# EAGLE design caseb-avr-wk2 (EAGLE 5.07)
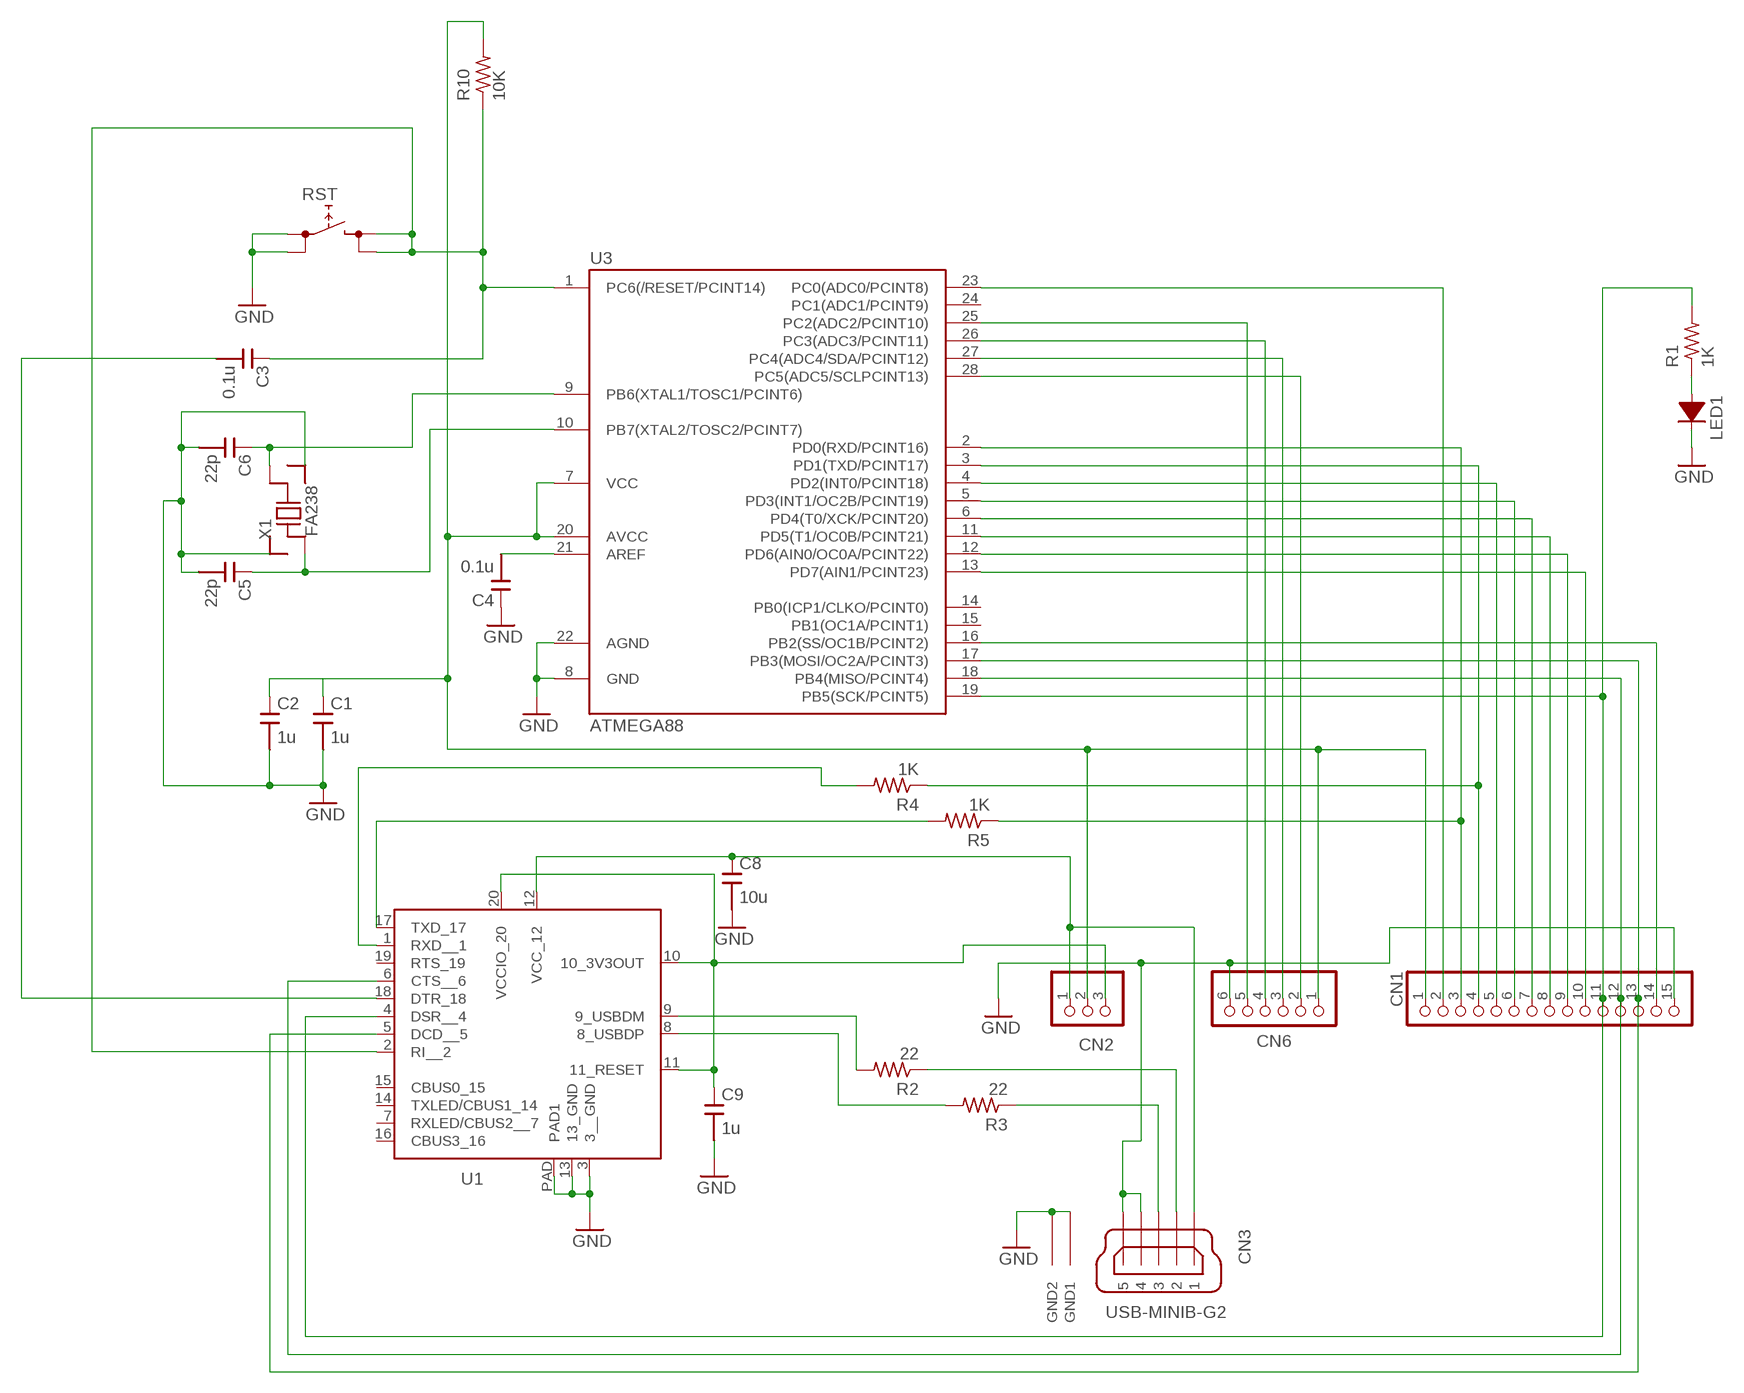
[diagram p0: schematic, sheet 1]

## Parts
C1  1u  C/SMDC2012  [C2012]
C2  1u  C/SMDC2012  [C2012]
C3  0.1u  C/SMDC2012  [C2012]
C4  0.1u  C/SMDC2012  [C2012]
C5  22p  C/SMDC2012  [C2012]
C6  22p  C/SMDC2012  [C2012]
C8  10u  C/SMDC2012  [C2012]
C9  1u  C/SMDC2012  [C2012]
CN1  PINHDR15  [PINHDRX15]
CN2  PINHDR3  [PINHDR1X3]
CN3  USB-MINIB-G2  [USB-MINIBV]
CN6  PINHDR6  [PINHDR1X6]
LED1  D/SMDRB161M  [SOD123]
R1  1K  R/SMDR2012R  [R2012R]
R2  22  R/SMDR2012R  [R2012R]
R3  22  R/SMDR2012R  [R2012R]
R4  1K  R/SMDR2012R  [R2012R]
R5  1K  R/SMDR2012R  [R2012R]
R10  10K  R/SMDR2012R  [R2012R]
RST  TACTSWTACTSW/SMD  [TACTSW/SMD]
U1  FT231XQ  [QFN20]
U3  ATMEGA88  [DIP28]
X1  FA238  [FA238]

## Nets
10_3V3OUT: C9.1 CN2.3 U1.10(10_3V3OUT) U1.11(11_RESET) U1.20(VCCIO_20)
GND [power]: C1.2 C2.2 C4.1 C5.2 C6.2 C8.2 C9.2 CN1.15 CN3.4 CN3.5 CN3.M1(GND1) CN3.M2(GND2) CN6.6 LED1.2(C) RST.1 RST.2 U1.3(3__GND) U1.13(13_GND) U1.PAD(PAD1) U3.8(GND) U3.22(AGND) X1.2 X1.4
N$1: CN1.2 U3.23(PC0(ADC0/PCINT8))
N$2: CN1.14 U3.16(PB2(SS/OC1B/PCINT2))
N$4: CN6.2 U3.28(PC5(ADC5/SCLPCINT13))
N$5: CN6.3 U3.27(PC4(ADC4/SDA/PCINT12))
N$6: LED1.1(A) R1.1
N$7: C3.1 R10.1 RST.3 RST.4 U1.2(RI__2) U3.1(PC6(/RESET/PCINT14))
N$10: CN1.11 R1.2 U1.4(DSR__4) U3.19(PB5(SCK/PCINT5))
N$11: CN1.3 R5.1 U3.2(PD0(RXD/PCINT16))
N$12: CN1.4 R4.1 U3.3(PD1(TXD/PCINT17))
N$13: CN1.5 U3.4(PD2(INT0/PCINT18))
N$14: CN6.4 U3.26(PC3(ADC3/PCINT11))
N$15: CN1.6 U3.5(PD3(INT1/OC2B/PCINT19))
N$16: C1.1 C2.1 CN1.1 CN2.2 CN6.1 R10.2 U3.7(VCC) U3.20(AVCC)
N$17: CN6.5 U3.25(PC2(ADC2/PCINT10))
N$18: C6.1 U3.9(PB6(XTAL1/TOSC1/PCINT6)) X1.3
N$19: CN1.7 U3.6(PD4(T0/XCK/PCINT20))
N$20: CN1.8 U3.11(PD5(T1/OC0B/PCINT21))
N$21: CN1.13 U1.5(DCD__5) U3.17(PB3(MOSI/OC2A/PCINT3))
N$22: C5.1 U3.10(PB7(XTAL2/TOSC2/PCINT7)) X1.1
N$23: CN1.10 U3.13(PD7(AIN1/PCINT23))
N$24: R5.2 U1.17(TXD_17)
N$25: CN3.2 R2.1
N$26: CN3.3 R3.1
N$27: R2.2 U1.9(9_USBDM)
N$28: R3.2 U1.8(8_USBDP)
N$29: R4.2 U1.1(RXD__1)
N$30: C3.2 U1.18(DTR_18)
N$31: C8.1 CN2.1 CN3.1 U1.12(VCC_12)
N$32: C4.2 U3.21(AREF)
N$33: CN1.9 U3.12(PD6(AIN0/OC0A/PCINT22))
N$34: CN1.12 U1.6(CTS__6) U3.18(PB4(MISO/PCINT4))
Unconnected: U1.7(RXLED/CBUS2__7) U1.14(TXLED/CBUS1_14) U1.15(CBUS0_15) U1.16(CBUS3_16) U1.19(RTS_19) U3.14(PB0(ICP1/CLKO/PCINT0)) U3.15(PB1(OC1A/PCINT1)) U3.24(PC1(ADC1/PCINT9))

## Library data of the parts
C1-C6 C8 C9 = SRT162-010:C/SMD
CN1 = SRT162-010:PINHDR15
CN2 = SRT162-010:PINHDR3
CN3 = SRT162-010:USB-MINIB-G2
CN6 = SRT162-010:PINHDR6
LED1 = SRT162-010:D/SMD
R1-R5 R10 = SRT162-010:R/SMD
RST = SRT162-010:TACTSW: 4pin tactsw (1,2 - 3,4)
U1 = SRT162-010:FT231XQ
U3 = SRT162-010:ATMEGA88
X1 = SRT162-010:FA238

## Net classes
0 default: width 0.203 mm
1 power: width 0.254 mm

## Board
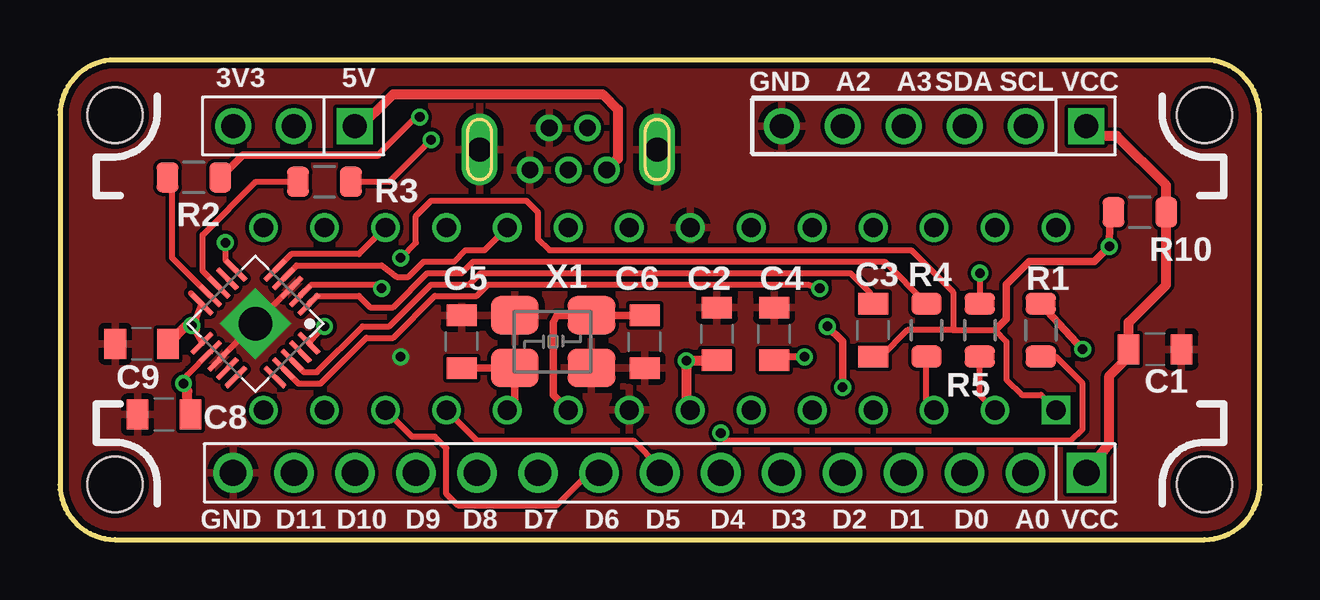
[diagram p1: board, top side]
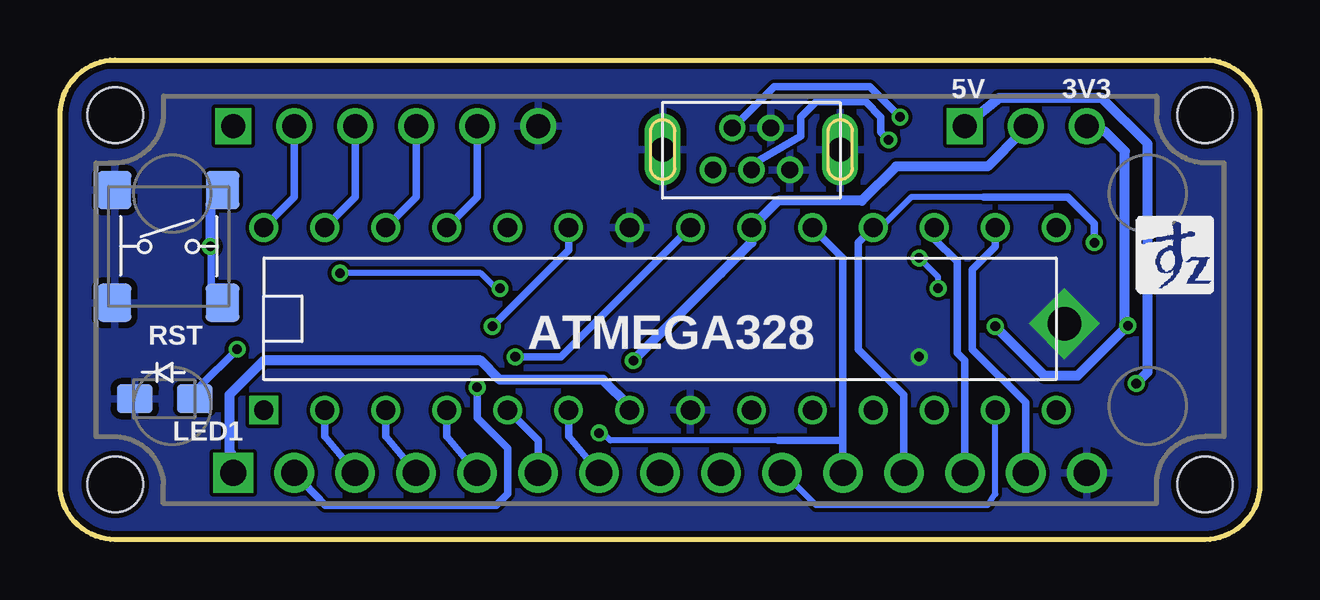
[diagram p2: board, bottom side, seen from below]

Size 49.99 x 20 mm. Coordinates in mm from the lower left corner, seen from the top.
Outline: 47.68,0 2.29,0 arc-90 0,2.3 0,17.7 arc-90 2.29,20 47.69,20 arc-90 49.98,17.7 49.98,2.3
Outline: 47.68,0 47.69,0
Outline: 47.68,0 arc90 49.99,2.3
Copper layers (1*16): Top 0.0356mm / dielectric 1.5011mm / Bottom 0.0356mm
Design rules "Fusion_v1.1 *": minimum track width 6mil, minimum drill 0.2997mm, track to track 6mil, track to pad 6mil, pad to pad 6mil, via to via 6mil, smd to smd 0mil, copper to edge 10mil, drill to drill 10mil, minimum pad ring 6mil, minimum via ring 6mil, stop-mask expansion 2mil, vias tented up to drill 100mil, thermal gap 10mil
Holes 2.3 mm at 47.69,17.7 2.29,17.7 2.29,2.3 47.69,2.3

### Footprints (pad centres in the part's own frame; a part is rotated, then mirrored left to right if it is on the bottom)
C2012 = smd 0.9 x 1.25: 1 -1.1,0; 2 1.1,0
PINHDRX15 = drill 1.1 square: 1 -17.78,0 | drill 1.1 round: 2 -15.24,0; 3 -12.7,0; 4 -10.16,0; 5 -7.62,0; 6 -5.08,0; 7 -2.54,0; 8 0,0; 9 2.54,0; 10 5.08,0; 11 7.62,0; 12 10.16,0; 13 12.7,0; 14 15.24,0; 15 17.78,0
PINHDR1X3 = drill 1 square: 1 -2.54,0 | drill 1 round: 2 0,0; 3 2.54,0
USB-MINIBV = drill 0.7 pad 1.1 round: 1 -0.995,1.6; 2 0.755,0.8; 3 -0.995,0; 4 0.755,-0.8; 5 -0.995,-1.6 | drill 1 long: M1 -0.145,3.7; M2 -0.145,-3.7
PINHDR1X6 = drill 1 square: 1 -6.35,0 | drill 1 round: 2 -3.81,0; 3 -1.27,0; 4 1.27,0; 5 3.81,0; 6 6.35,0
SOD123 = smd 1.5 x 1.2: 1 -1.25,0; 2 1.25,0
R2012R = smd 0.9 x 1.25: 1 -1.1,0; 2 1.1,0
TACTSW/SMD = smd 1.4 x 1.6: 1 -2.25,2.35; 2 -2.25,-2.35; 3 2.25,2.35; 4 2.25,-2.35
QFN20 = smd 1.2 x 0.25: 1 -2.15,1; 2 -2.15,0.5; 3 -2.15,0; 4 -2.15,-0.5; 5 -2.15,-1; 11 2.15,-1; 12 2.15,-0.5; 13 2.15,0; 14 2.15,0.5; 15 2.15,1 | smd 0.25 x 1.2: 6 -1,-2.15; 7 -0.5,-2.15; 8 0,-2.15; 9 0.5,-2.15; 10 1,-2.15; 16 1,2.15; 17 0.5,2.15; 18 0,2.15; 19 -0.5,2.15; 20 -1,2.15 | drill 1.4 pad 2.1 square: PAD 0,0
DIP28 = drill 0.8 square: 1 -16.51,-3.81 | drill 0.8 round: 2 -13.97,-3.81; 3 -11.43,-3.81; 4 -8.89,-3.81; 5 -6.35,-3.81; 6 -3.81,-3.81; 7 -1.27,-3.81; 8 1.27,-3.81; 9 3.81,-3.81; 10 6.35,-3.81; 11 8.89,-3.81; 12 11.43,-3.81; 13 13.97,-3.81; 14 16.51,-3.81; 15 16.51,3.81; 16 13.97,3.81; 17 11.43,3.81; 18 8.89,3.81; 19 6.35,3.81; 20 3.81,3.81; 21 1.27,3.81; 22 -1.27,3.81; 23 -3.81,3.81; 24 -6.35,3.81; 25 -8.89,3.81; 26 -11.43,3.81; 27 -13.97,3.81; 28 -16.51,3.81
FA238 = smd 2 x 1.6: 1 -1.6,-1.1; 2 1.6,-1.1; 3 1.6,1.1; 4 -1.6,1.1

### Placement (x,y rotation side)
C1  45.63,7.94 0 top
C2  27.37,8.57 90 top
C3  33.88,8.73 90 top
C4  29.75,8.57 270 top
C5  16.74,8.25 90 top
C6  24.35,8.25 270 top
C8  4.33,5.22 180 top
C9  3.4,8.16 180 top
CN1  24.99,2.78 180 top
CN2  9.75,17.25 180 top
CN3  21.18,16.41 90 bottom
CN6  36.42,17.25 180 top
LED1  45.63,5.87 180 bottom
R1  40.87,8.73 270 top
R2  5.58,15.1 180 top
R3  11.02,14.92 180 top
R4  36.1,8.73 90 top
R5  38.33,8.73 90 top
R10  44.99,13.65 0 top
RST  45.47,12.22 0 bottom
U1  8.14,9 225 top
U3  24.99,9.21 0 bottom
X1  20.55,8.25 0 top

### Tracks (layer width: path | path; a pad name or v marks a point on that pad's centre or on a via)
10_3V3OUT  (via drill 0.4)
  Top 0.254: U1.20 10.44,8.25 v11.02,8.89 | U1.11 v5.5,8.92 5.7,8.81 5.7,9.28 U1.10 5.45,10.28
  Top 0.406: 5.63,8.74 v5.5,8.92 5.26,8.92 C9.1
  Bottom 0.406: v11.02,8.89 10.7,8.57 8.96,6.82 7.6,6.82 v5.5,8.92 5.62,8.8 5.62,16.19 6.42,16.98 CN2.3
GND  (via drill 0.4)
  Top 0.254: U1.13 U1.PAD U1.3 | X1.4 18.64,10
  other vias: 14.2,7.62
  pour Bottom: -2.31,-2.7 51.98,-2.7 51.98,21.43 -2.31,21.43
  pour Top: 51.02,21.11 -1.36,21.11 -1.36,-1.11 51.02,-1.11
N$1  (via drill 0.4)
  Top 0.305: v31.98,8.89 32.61,8.25 v32.61,6.35
  Bottom 0.305: U3.23 28.8,12.06 v31.98,8.89 | CN1.2 38.95,1.43 31.82,1.43 31.34,1.9 31.34,3.81 32.61,5.08 v32.61,6.35
N$2
  Bottom 0.305: CN1.14 9.75,5.71 11.97,7.94 11.97,11.27 11.02,12.22 U3.16
N$4
  Bottom 0.305: U3.28 40.23,14.29 CN6.2
N$5
  Bottom 0.305: U3.27 37.69,14.29 CN6.3
N$6  (via drill 0.4)
  Top 0.305: R1.1 v42.61,7.94
  Bottom 0.305: LED1.1 44.2,6.35 v42.61,7.94
N$7  (via drill 0.4)
  Top 0.203: 43.64,12.14 v43.72,12.22
  Top 0.254: C3.1 34.21,7.63 35.31,8.73 37.21,8.73 | 37.21,8.73 38.96,8.73 39.44,8.25 39.44,6.67 40.07,6.03 40.87,6.03 U3.1 | U1.2 10.48,10.64 13.24,10.64 v13.4,10.48 | 37.21,8.73 37.21,10.32 35.47,12.06 20.39,12.06 19.91,12.54 19.91,13.65 19.43,14.13 15.46,14.13 14.83,13.49 14.83,12.38 v14.2,11.75
  Top 0.305: R10.1 43.73,13.19 v43.72,12.22 | 43.64,12.14 43.09,11.59 40.39,11.59 | 40.39,11.59 | 40.39,11.59 39.44,10.64 39.44,9.21 38.96,8.73 | 38.96,8.73
  Bottom 0.203: 43.41,14.6 RST.3
  Bottom 0.254: v13.4,10.48 13.4,10.95 v14.2,11.75
  Bottom 0.305: 43.25,14.6 43.72,13.81 v43.72,12.22 43.7,12.04 43.7,9.71 RST.4 | 43.09,14.45 43.53,14.89 RST.3
  Bottom 0.406: 43.41,14.6 43.25,14.6 43.72,13.97 43.72,12.44
N$10  (via drill 0.4)
  Top 0.254: R1.2 41.49,7.63 42.61,6.51 42.61,4.6 42.13,4.13 27.69,4.13 v27.53,4.44 | U3.19 17.69,12.06 16.89,12.06 16.42,11.59 15.15,11.59 14.51,10.95 14.04,10.95 13.4,11.43 9.86,11.43 U1.4
  Bottom 0.254: 20.07,4.13 27.05,4.13 27.37,4.44 v27.53,4.44
  Bottom 0.305: 17.37,4.13 CN1.11 | 17.37,4.13 20.07,4.13 | 17.37,4.13 17.37,11.75 U3.19
N$11
  Top 0.254: R5.1 38.33,6.03 U3.2
  Bottom 0.305: U3.2 38.96,4.3 CN1.3
N$12
  Top 0.254: R4.1 36.1,5.71 U3.3
  Bottom 0.305: U3.3 36.42,4.3 CN1.4
N$13
  Bottom 0.305: U3.4 33.88,4.3 CN1.5
N$14
  Bottom 0.305: U3.26 35.15,14.29 CN6.4
N$15
  Bottom 0.305: U3.5 30.07,4.13 CN1.6
N$16  (via drill 0.4)
  Top 0.203: C1.1 44.52,7.86 44.6,7.7
  Top 0.406: U3.7 26.1,5.55 v26.1,7.46 26.11,7.47 C2.1 | 44.6,7.7 43.72,6.82 43.72,3.98 CN1.1 | C1.1 44.53,9.06 46.09,10.62 R10.2 46.09,14.77 44.04,16.83 42.94,16.83 CN6.1
  Bottom 0.203: CN1.1 42.77,3.65 42.93,3.65
  Bottom 0.406: U3.7 26.26,5.55 27.37,6.67 31.66,6.67 32.45,7.46 41.5,7.46 42.93,6.03 42.93,3.65 42.93,3.19 | CN2.2 9.91,16.98 11.34,15.56 15.15,15.56 16.58,14.13 20.07,14.13 U3.20 21.18,12.38 22.45,11.11 v26.1,7.46 | v26.1,7.46
N$17
  Bottom 0.305: U3.25 32.61,14.29 CN6.5
N$18
  Top 0.305: U3.9 20.54,6.03 20.54,9.05 20.69,9.35 X1.3 C6.1
N$19
  Bottom 0.305: U3.6 28.8,4.3 CN1.7
N$20
  Top 0.254: U3.11 17.37,4.13 23.88,4.13 24.98,3.03 CN1.8
N$21
  Top 0.254: U1.5 9.63,11.91 12.45,11.91 U3.17 13.56,12.54
  Bottom 0.305: CN1.13 12.29,7.46 12.61,7.78 12.61,11.59 13.56,12.54 U3.17
N$22
  Top 0.305: C5.1 17.05,7.15 X1.1 18.95,5.7 U3.10
N$23
  Bottom 0.254: CN1.10 19.91,2.86 18.48,1.43 11.34,1.43 11.02,1.9 U3.13
N$24  (via drill 0.4)
  Top 0.254: v38.33,11.11 | v31.66,10.48 31.18,10.64 17.85,10.64 17.37,10.16 15.62,10.16 13.88,8.41 12.77,8.41 10.86,6.51 9.93,6.51 U1.17 | v38.33,11.11 R5.2
  Bottom 0.254: v31.66,10.48 31.82,10.48 32.45,11.11 v38.33,11.11 | v38.33,11.11
N$25  (via drill 0.4)
  Top 0.254: 13.24,16.03 14.83,17.62 v14.99,17.62
  Top 0.305: R2.1 7.61,16.03 13.24,16.03 | v14.99,17.62 14.99,17.46
  Bottom 0.305: v14.99,17.62 16.26,18.89 20.23,18.89 21.95,17.16 CN3.2
N$26  (via drill 0.4)
  Top 0.254: v15.46,16.67 | v15.46,16.67 13.72,14.92 R3.1 | R3.1
  Bottom 0.305: CN3.3 21.04,15.56 21.02,15.71 19.12,16.83 19.12,17.62 18.48,18.25 16.42,18.25 15.78,17.62 15.78,16.98 v15.46,16.67
N$27
  Top 0.254: U1.9 6.25,10.17 4.67,11.75 4.67,14.43 R2.2
N$28
  Top 0.254: U1.8 5.94,11.2 5.94,12.7 8.16,14.92 9.76,14.92 R3.2
N$29
  Top 0.254: R4.2 36.1,9.84 34.36,11.59 17.21,11.59 16.73,11.11 15.31,11.11 13.88,9.68 12.93,9.68 12.45,10.16 10.71,10.16 U1.1
N$30
  Top 0.254: C3.2 33.72,10.32 32.93,11.11 17.53,11.11 17.05,10.64 15.46,10.64 13.72,8.89 12.61,8.89 10.7,6.98 10.16,6.98 U1.18
N$31  (via drill 0.4)
  Top 0.254: U1.12 5.3,6.87 v5.15,6.51
  Top 0.406: CN3.1 23.24,15.88 23.24,17.94 22.61,18.57 13.88,18.57 12.29,16.98 CN2.1 | v5.15,6.51 5.3,6.19 5.32,5.54 C8.1
  Bottom 0.406: CN2.1 10.86,18.41 6.57,18.41 4.67,16.51 4.67,6.98 v5.15,6.51 | v5.15,6.51
N$32  (via drill 0.4)
  Top 0.305: v31.02,7.62 29.92,7.63 C4.2
  Bottom 0.305: U3.21 29.12,7.62 v31.02,7.62
N$33
  Top 0.254: U3.12 14.67,4.29 15.62,4.29 16.1,3.81 16.1,1.9 16.58,1.43 20.7,1.43 22.31,3.03 CN1.9
N$34  (via drill 0.4)
  Top 0.254: U1.6 6.89,11.67 v6.89,12.38
  Bottom 0.254: 11.5,14.29 14.51,14.29 15.78,13.02 U3.18
  Bottom 0.305: CN1.12 14.83,6.03 16.73,7.94 16.73,12.38 U3.18 | 11.5,14.29 8,14.29 6.89,13.18 v6.89,12.38

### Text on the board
tPlace: 3V3 | 5V | GND | A2 | A3 | SDA | SCL | VCC | GND | D11 | D10 | D9 | D8 | D7 | D6 | D5 | D4 | D3 | D2 | D1 | D0 | A0 | VCC
bPlace: 3V3 | 5V | ATMEGA328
